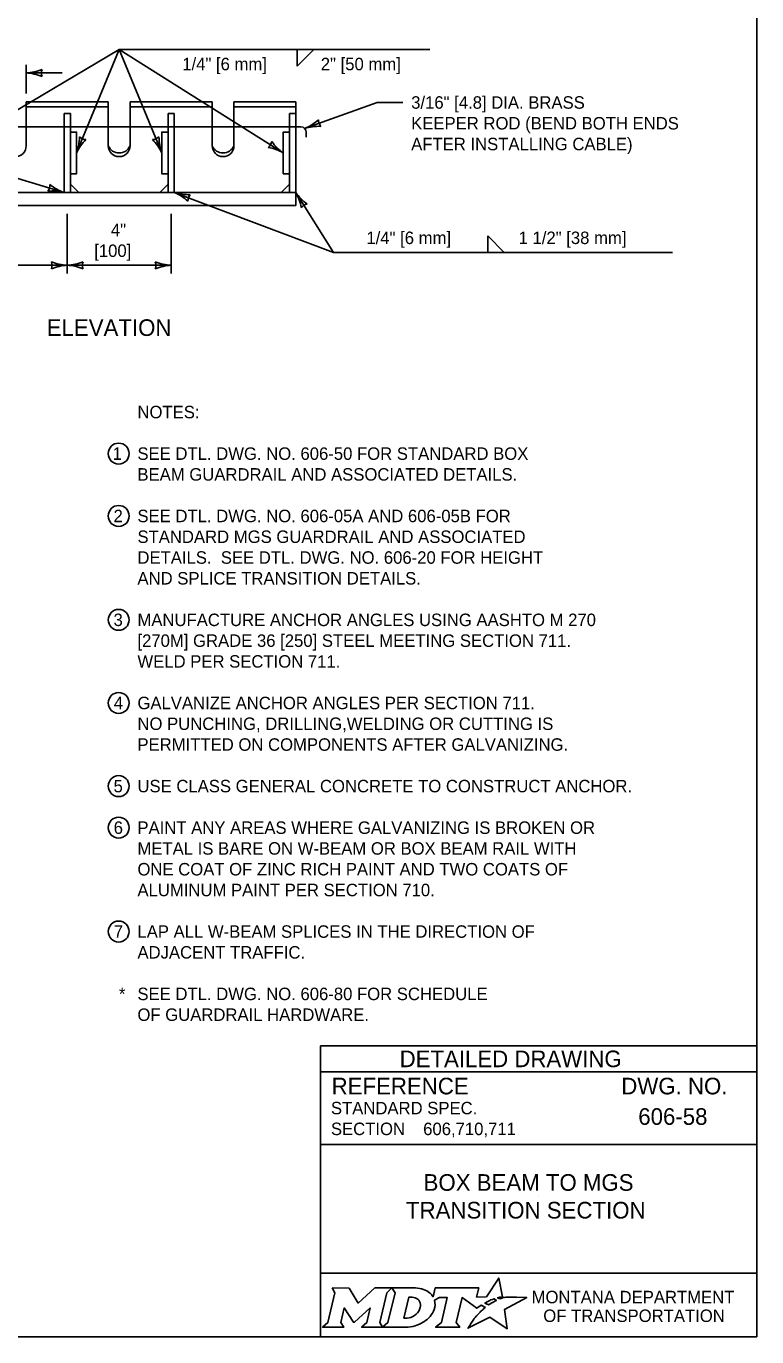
# Model space of a CAD drawing. Extents: x 49991.4 to 50021, y 49987.6 to 50011.4.
# Drawn here: x 50013.23 to 50016.75, y 49987.8 to 49994.11 of the extents above; entities that cross this region are included whole.
import ezdxf

# ---------------------------------------------------------------- set-up
doc = ezdxf.new("R2010")
doc.units = 0
for name, color, linetype in [('Default', 7, 'Continuous'), ('Level 1', 7, 'Continuous'), ('Level 2', 7, 'Continuous'), ('Level 3', 7, 'Continuous'), ('Level 4', 7, 'Continuous'), ('Level 5', 7, 'Continuous')]:
    doc.layers.add(name, color=color, linetype=linetype)

msp = doc.modelspace()

# ---------------------------------------------------------------- linework, layer by layer
at = {"layer": 'Default'}
for points in [[(50015.5126, 49987.9811), (50015.5023, 49987.9867), (50015.5139, 49987.9895), (50015.5255, 49987.9915), (50015.5081, 49988.0816), (50015.4486, 49987.9903), (50015.4013, 49987.9896), (50015.4116, 49988.0337), (50015.2024, 49988.0338), (50015.1923, 49987.9913), (50015.1865, 49987.9996)], [(50014.7056, 49988.0338), (50014.7197, 49988.0104), (50014.6862, 49987.8671), (50014.6605, 49987.8446), (50014.7621, 49987.8446), (50014.7486, 49987.8674), (50014.7648, 49987.9375), (50014.8085, 49987.8685), (50014.8138, 49987.8685), (50014.8889, 49987.938), (50014.8725, 49987.8669), (50014.8478, 49987.8449), (50014.9494, 49987.8449), (50014.9356, 49987.8682), (50014.9688, 49988.0106)], [(50014.9688, 49988.0106), (50014.9941, 49988.0338), (50014.9117, 49988.0338), (50014.8321, 49987.9608), (50014.7876, 49988.0335), (50014.7056, 49988.0338)], [(50015.1077, 49988.0338), (50014.9941, 49988.0338), (50015.0088, 49988.0109), (50014.9749, 49987.8671), (50014.9494, 49987.8449), (50015.06, 49987.8449)], [(50015.1317, 49987.9471), (50015.1305, 49987.939), (50015.1273, 49987.9297), (50015.1231, 49987.9215), (50015.1175, 49987.914), (50015.111, 49987.9071), (50015.1031, 49987.9008), (50015.0948, 49987.8961), (50015.0857, 49987.8922), (50015.0766, 49987.8899), (50015.0674, 49987.889), (50015.0515, 49987.889), (50015.0751, 49987.989), (50015.0911, 49987.989), (50015.0987, 49987.9884), (50015.1063, 49987.9865), (50015.1129, 49987.9835), (50015.119, 49987.9793), (50015.1238, 49987.9743), (50015.1275, 49987.9683), (50015.1302, 49987.9621), (50015.1318, 49987.9547), (50015.1318, 49987.9517), (50015.1317, 49987.9471)], [(50015.1991, 49987.9747), (50015.2237, 49987.9878), (50015.2606, 49987.9878), (50015.232, 49987.8673), (50015.2045, 49987.8446), (50015.3207, 49987.8446), (50015.3037, 49987.8675), (50015.3319, 49987.9877), (50015.4032, 49987.936), (50015.4243, 49987.9511), (50015.444, 49987.9402)], [(50015.3882, 49987.8843), (50015.3729, 49987.8599), (50015.3682, 49987.8524), (50015.3624, 49987.8438), (50015.3601, 49987.8395), (50015.4654, 49987.8926), (50015.5493, 49987.8375), (50015.5362, 49987.9302), (50015.6431, 49987.9886), (50015.5938, 49987.9894), (50015.5637, 49987.9898), (50015.5429, 49987.9901), (50015.5361, 49987.9886), (50015.5312, 49987.9874), (50015.5228, 49987.9851), (50015.5126, 49987.9811)], [(50015.4622, 49987.9535), (50015.4598, 49987.9518), (50015.4415, 49987.9614), (50015.4518, 49987.9671), (50015.4559, 49987.9693), (50015.4645, 49987.9733), (50015.4702, 49987.9759), (50015.4781, 49987.9789), (50015.4854, 49987.9816), (50015.4972, 49987.9742), (50015.4932, 49987.9721), (50015.4886, 49987.9696), (50015.4844, 49987.9674), (50015.4794, 49987.9645), (50015.4775, 49987.9634), (50015.4748, 49987.9618), (50015.4723, 49987.9604), (50015.47, 49987.9588), (50015.4674, 49987.957), (50015.4647, 49987.9552), (50015.4622, 49987.9535)], [(50015.4021, 49987.9004), (50015.4021, 49987.9004)], [(50015.1057, 49987.8522), (50015.1141, 49987.8548), (50015.1271, 49987.8602), (50015.1475, 49987.8712)]]:
    msp.add_lwpolyline(points, dxfattribs=at)
for centre, radius, start, end in [((50015.1308, 49987.9554), 0.0709, 339.53292, 15.85821), ((50015.0868, 49987.9727), 0.1183, 300.91025, 339.13831)]:
    msp.add_arc(centre, radius, start, end, dxfattribs=at)
for centre, major_axis, ratio, start_param, end_param in [((50015.1056, 49987.9864), (0.0834, -0.0037), 0.568097, 0.61298, 1.570796), ((50015.1612, 49987.9937), (0.0361, -0.0295), 0.469099, 1.225588, 1.570796), ((50015.3952, 49987.8923), (-0.00694, -0.00806), 0.008222, 0, 3.137361), ((50015.4119, 49987.9106), (-0.0098, -0.0102), 0.016458, 3.141593, 6.279097), ((50015.4329, 49987.9305), (-0.0112, -0.0097), 0.021651, 3.157348, 6.283185), ((50015.0603, 49987.9932), (0, 0.1484), 0.987302, 3.139398, 3.456847)]:
    msp.add_ellipse(centre, major_axis=major_axis, ratio=ratio, start_param=start_param, end_param=end_param, dxfattribs=at)
at = {"layer": 'Level 1'}
for p, q in [((50013.2338, 49993.7421), (50013.2338, 49993.5306)), ((50013.6288, 49993.7421), (50013.2338, 49993.7421)), ((50013.2338, 49993.7181), (50013.6288, 49993.7181)), ((50013.6288, 49993.7421), (50013.6288, 49993.5306)), ((50013.7338, 49993.7421), (50013.7338, 49993.5306)), ((50014.1288, 49993.7421), (50013.7338, 49993.7421)), ((50013.7338, 49993.7181), (50014.1288, 49993.7181)), ((50014.1288, 49993.7421), (50014.1288, 49993.5306)), ((50014.2338, 49993.7421), (50014.2338, 49993.5306)), ((50014.5313, 49993.7421), (50014.2338, 49993.7421)), ((50014.2338, 49993.7181), (50014.5313, 49993.7181)), ((50014.5313, 49993.2426), (50014.5313, 49993.7421)), ((50013.4163, 49993.6861), (50013.4163, 49993.3061)), ((50013.4163, 49993.6861), (50013.4463, 49993.6861)), ((50013.4463, 49993.6861), (50013.4463, 49993.3061)), ((50013.9163, 49993.6861), (50013.9163, 49993.3061)), ((50013.9163, 49993.6861), (50013.9463, 49993.6861)), ((50013.9463, 49993.6861), (50013.9463, 49993.3061)), ((50014.5013, 49993.6861), (50014.5013, 49993.3061)), ((50014.5013, 49993.6861), (50014.5313, 49993.6861)), ((50012.8113, 49993.6211), (50013.4163, 49993.6211)), ((50013.4463, 49993.6211), (50013.9163, 49993.6211)), ((50013.4463, 49993.5961), (50013.4763, 49993.5961)), ((50013.4763, 49993.3961), (50013.4763, 49993.5961)), ((50013.9163, 49993.5961), (50013.8863, 49993.5961)), ((50013.8863, 49993.3961), (50013.8863, 49993.5961)), ((50013.9463, 49993.6211), (50014.5013, 49993.6211)), ((50014.5013, 49993.5961), (50014.4713, 49993.5961)), ((50014.4713, 49993.3961), (50014.4713, 49993.5961)), ((50014.5313, 49993.6211), (50014.5563, 49993.6211)), ((50014.5813, 49993.5961), (50014.5813, 49993.5711)), ((50013.4463, 49993.3961), (50013.4763, 49993.3961)), ((50013.9163, 49993.3961), (50013.8863, 49993.3961)), ((50014.5013, 49993.3961), (50014.4713, 49993.3961)), ((50013.4863, 49993.3061), (50013.4463, 49993.3461)), ((50013.8763, 49993.3061), (50013.9163, 49993.3461)), ((50014.4613, 49993.3061), (50014.5013, 49993.3461)), ((50012.7813, 49993.3061), (50014.5313, 49993.3061)), ((50012.7813, 49993.2426), (50014.5313, 49993.2426))]:
    msp.add_line(p, q, dxfattribs=at)
msp.add_lwpolyline([(49999.3835, 49998.9992), (50016.7501, 49998.9992), (50016.7501, 49987.7988), (49999.3835, 49987.7988)], close=True, dxfattribs=at)
for points in [[(50013.4463, 49993.5961), (50013.4463, 49993.3961), (50013.4763, 49993.3961), (50013.4763, 49993.5961), (50013.4463, 49993.5961)], [(50013.9163, 49993.3961), (50013.9163, 49993.5961), (50013.8863, 49993.5961), (50013.8863, 49993.3961), (50013.9163, 49993.3961)], [(50014.5013, 49993.3961), (50014.5013, 49993.5961), (50014.4713, 49993.5961), (50014.4713, 49993.3961), (50014.5013, 49993.3961)], [(50013.4463, 49993.3061), (50013.4863, 49993.3061), (50013.4463, 49993.3461), (50013.4463, 49993.3061)], [(50013.8763, 49993.3061), (50013.9163, 49993.3061), (50013.9163, 49993.3461), (50013.8763, 49993.3061)], [(50014.4613, 49993.3061), (50014.5013, 49993.3061), (50014.5013, 49993.3461), (50014.4613, 49993.3061)]]:
    msp.add_lwpolyline(points, dxfattribs=at)
for centre, radius, start, end in [((50014.5563, 49993.5961), 0.025, 0, 90), ((50013.1813, 49993.5306), 0.0525, 270, 0), ((50013.6813, 49993.5306), 0.0525, 180, 270), ((50013.6813, 49993.5525), 0.0569, 202.61987, 337.38013), ((50013.6813, 49993.5306), 0.0525, 270, 0), ((50014.1813, 49993.5306), 0.0525, 180, 270), ((50014.1813, 49993.5525), 0.0569, 202.61986, 337.38014), ((50014.1813, 49993.5306), 0.0525, 270, 0)]:
    msp.add_arc(centre, radius, start, end, dxfattribs=at)
at = {"layer": 'Level 2'}
for centre in [(50013.6789, 49992.0489), (50013.6789, 49991.7489), (50013.6789, 49991.2489), (50013.6789, 49990.8489), (50013.6789, 49990.4489), (50013.6789, 49990.2489), (50013.6789, 49989.7489)]:
    msp.add_circle(centre, 0.0503, dxfattribs=at)
at = {"layer": 'Level 3'}
for p, q in [((50013.6813, 49993.9937), (50012.8413, 49993.4961)), ((50013.6813, 49993.9937), (50013.4763, 49993.4961)), ((50013.6813, 49993.9937), (50015.176, 49993.9937)), ((50013.6813, 49993.9937), (50013.8863, 49993.4961)), ((50013.6813, 49993.9937), (50014.4713, 49993.4961)), ((50014.5385, 49993.9137), (50014.6185, 49993.9937)), ((50014.5385, 49993.9937), (50014.5385, 49993.9137)), ((50013.2338, 49993.7821), (50013.2338, 49993.9206)), ((50013.2338, 49993.8806), (50013.4072, 49993.8806)), ((50014.574, 49993.6138), (50014.9223, 49993.7387)), ((50014.9223, 49993.7387), (50015.0467, 49993.7387)), ((50012.4821, 49993.5846), (50013.4163, 49993.3061)), ((50013.9463, 49993.3061), (50014.7126, 49993.0174)), ((50014.5313, 49993.3061), (50014.7126, 49993.0174)), ((50013.4313, 49992.9153), (50013.4313, 49993.2026)), ((50013.9313, 49992.9153), (50013.9313, 49993.2026)), ((50015.455, 49993.0174), (50015.455, 49993.0974)), ((50015.455, 49993.0974), (50015.535, 49993.0174)), ((50014.7126, 49993.0174), (50016.345, 49993.0174)), ((50012.7813, 49992.9553), (50013.4313, 49992.9553)), ((50013.4313, 49992.9553), (50013.9313, 49992.9553))]:
    msp.add_line(p, q, dxfattribs=at)
for centre, radius, start, end in [((50013.2223, 49994.1133), 0.233, 272.82731, 292.07716), ((50013.2246, 49993.6585), 0.2223, 67.45601, 87.63952), ((50013.362, 49993.8806), 0.0548, 162.13882, 197.86118), ((50014.4846, 49993.8289), 0.233, 292.55528, 311.80513), ((50014.6947, 49993.657), 0.0548, 181.86679, 217.58915), ((50013.2568, 49993.5741), 0.233, 340.43735, 359.6872), ((50013.5251, 49993.6146), 0.0548, 229.74886, 265.47122), ((50013.8375, 49993.6146), 0.0548, 274.52878, 310.25114), ((50014.0952, 49993.5722), 0.2223, 179.84597, 200.02948), ((50014.6403, 49993.4016), 0.2223, 87.18398, 107.36749), ((50013.6782, 49993.403), 0.2223, 135.06605, 155.24956), ((50013.6755, 49993.3968), 0.233, 25.21727, 44.46712), ((50014.3628, 49993.5644), 0.0548, 309.93232, 345.65468), ((50014.357, 49993.2931), 0.233, 60.62081, 79.87066), ((50014.5974, 49993.6792), 0.2223, 215.24951, 235.43302), ((50013.2934, 49993.3427), 0.0548, 325.53875, 1.26112), ((50013.3608, 49993.0798), 0.233, 76.22725, 95.4771), ((50013.4885, 49993.5163), 0.2223, 230.85595, 251.03945), ((50013.8594, 49993.1014), 0.2223, 46.80997, 66.99348), ((50014.0176, 49993.5279), 0.233, 252.18127, 271.43112), ((50014.0663, 49993.2609), 0.0548, 141.49278, 177.21514), ((50014.3383, 49993.1957), 0.2223, 9.57633, 29.75984), ((50014.7223, 49993.4396), 0.233, 214.94763, 234.19748), ((50014.5995, 49993.1975), 0.0548, 104.25914, 139.9815), ((50013.4405, 49993.1774), 0.2223, 247.45601, 267.63952), ((50013.3031, 49992.9553), 0.0548, 342.13882, 17.86118), ((50013.4428, 49992.7226), 0.233, 92.82731, 112.07716), ((50013.4198, 49993.188), 0.233, 272.82731, 292.07716), ((50013.4221, 49992.7332), 0.2223, 67.45601, 87.63952), ((50013.5595, 49992.9553), 0.0548, 162.13882, 197.86118), ((50013.9405, 49993.1774), 0.2223, 247.45601, 267.63952), ((50013.8031, 49992.9553), 0.0548, 342.13882, 17.86118), ((50013.9428, 49992.7226), 0.233, 92.82731, 112.07716)]:
    msp.add_arc(centre, radius, start, end, dxfattribs=at)
at = {"layer": 'Level 4'}
for p, q in [((50013.4163, 49993.6211), (50013.4463, 49993.6211)), ((50013.9163, 49993.6211), (50013.9463, 49993.6211)), ((50014.5013, 49993.6211), (50014.5313, 49993.6211))]:
    msp.add_line(p, q, dxfattribs=at)
at = {"layer": 'Level 5'}
for p, q in [((50016.7501, 49989.1988), (50014.6501, 49989.1988)), ((50014.6501, 49989.1988), (50014.6501, 49987.7988)), ((50016.7501, 49989.0738), (50014.6501, 49989.0738)), ((50016.3862, 49988.8587), (50016.3862, 49988.8587)), ((50015.1444, 49988.7993), (50015.1444, 49988.7993)), ((50016.7501, 49988.7238), (50014.6501, 49988.7238)), ((50015.7001, 49988.4747), (50015.7001, 49988.4747)), ((50016.7501, 49988.1057), (50014.6501, 49988.1057))]:
    msp.add_line(p, q, dxfattribs=at)

# ---------------------------------------------------------------- texts
at = {"layer": 'Default'}
for s, p in [('MONTANA DEPARTMENT', (50015.6663, 49987.96)), ('OF TRANSPORTATION', (50015.7225, 49987.87))]:
    msp.add_text(s, height=0.06, dxfattribs=at).set_placement(p)
at = {"layer": 'Level 2'}
for s, height, p in [('1/4" [6 mm]', 0.06, (50013.9848, 49993.8937)), ('2" [50 mm]', 0.06, (50014.6516, 49993.8937)), ('3/16" [4.8] DIA. BRASS', 0.06, (50015.0867, 49993.7087)), ('KEEPER ROD (BEND BOTH ENDS', 0.06, (50015.0867, 49993.6087)), ('AFTER INSTALLING CABLE)', 0.06, (50015.0867, 49993.5087)), ('4"', 0.06, (50013.6411, 49993.0953)), ('1/4" [6 mm]', 0.06, (50014.8712, 49993.0574)), ('1 1/2" [38 mm]', 0.06, (50015.6038, 49993.0574)), ('[100]', 0.06, (50013.5612, 49992.9953)), ('ELEVATION', 0.08, (50013.3325, 49992.6152)), ('NOTES:', 0.06, (50013.7692, 49992.2189)), ('1', 0.06, (50013.6495, 49992.0189)), ('SEE DTL. DWG. NO. 606-50 FOR STANDARD BOX ', 0.06, (50013.7692, 49992.0189)), ('BEAM GUARDRAIL AND ASSOCIATED DETAILS.', 0.06, (50013.7692, 49991.9189)), ('2', 0.06, (50013.6541, 49991.719)), ('SEE DTL. DWG. NO. 606-05A AND 606-05B FOR ', 0.06, (50013.7692, 49991.7189)), ('STANDARD MGS GUARDRAIL AND ASSOCIATED', 0.06, (50013.7692, 49991.6189)), ('DETAILS.  SEE DTL. DWG. NO. 606-20 FOR HEIGHT', 0.06, (50013.7692, 49991.5189)), ('AND SPLICE TRANSITION DETAILS.', 0.06, (50013.7692, 49991.4189)), ('3', 0.06, (50013.6541, 49991.219)), ('MANUFACTURE ANCHOR ANGLES USING AASHTO M 270', 0.06, (50013.7692, 49991.2189)), ('[270M] GRADE 36 [250] STEEL MEETING SECTION 711.', 0.06, (50013.7692, 49991.1189)), ('WELD PER SECTION 711.', 0.06, (50013.7692, 49991.0189)), ('4', 0.06, (50013.6553, 49990.819)), ('GALVANIZE ANCHOR ANGLES PER SECTION 711.  ', 0.06, (50013.7692, 49990.8189)), ('NO PUNCHING, DRILLING,WELDING OR CUTTING IS ', 0.06, (50013.7692, 49990.7189)), ('PERMITTED ON COMPONENTS AFTER GALVANIZING.', 0.06, (50013.7692, 49990.6189)), ('5', 0.06, (50013.6544, 49990.419)), ('USE CLASS GENERAL CONCRETE TO CONSTRUCT ANCHOR.', 0.06, (50013.7692, 49990.4189)), ('6', 0.06, (50013.6548, 49990.219)), ('PAINT ANY AREAS WHERE GALVANIZING IS BROKEN OR ', 0.06, (50013.7692, 49990.2189)), ('METAL IS BARE ON W-BEAM OR BOX BEAM RAIL WITH ', 0.06, (50013.7692, 49990.1189)), ('ONE COAT OF ZINC RICH PAINT AND TWO COATS OF ', 0.06, (50013.7692, 49990.0189)), ('ALUMINUM PAINT PER SECTION 710. ', 0.06, (50013.7692, 49989.9189)), ('7', 0.06, (50013.6555, 49989.719)), ('LAP ALL W-BEAM SPLICES IN THE DIRECTION OF ', 0.06, (50013.7692, 49989.7189)), ('ADJACENT TRAFFIC.', 0.06, (50013.7692, 49989.6189)), ('*', 0.06, (50013.68, 49989.4189)), ('SEE DTL. DWG. NO. 606-80 FOR SCHEDULE ', 0.06, (50013.7692, 49989.4189)), ('OF GUARDRAIL HARDWARE.', 0.06, (50013.7692, 49989.3189)), ('606-58', 0.08, (50016.1797, 49988.8187)), ('606,710,711', 0.06, (50015.1444, 49988.7693)), ('BOX BEAM TO MGS', 0.08, (50015.1464, 49988.5014)), ('TRANSITION SECTION', 0.08, (50015.0617, 49988.368))]:
    msp.add_text(s, height=height, dxfattribs=at).set_placement(p)
at = {"layer": 'Level 5'}
for s, height, p in [('DETAILED DRAWING', 0.0799, (50015.0311, 49989.0963)), ('REFERENCE', 0.08, (50014.7037, 49988.9654)), ('DWG. NO.', 0.08, (50016.0979, 49988.9654)), ('STANDARD SPEC.', 0.06, (50014.7004, 49988.8694)), ('SECTION', 0.06, (50014.7004, 49988.7694))]:
    msp.add_text(s, height=height, dxfattribs=at).set_placement(p)

doc.saveas('drawing.dxf')
